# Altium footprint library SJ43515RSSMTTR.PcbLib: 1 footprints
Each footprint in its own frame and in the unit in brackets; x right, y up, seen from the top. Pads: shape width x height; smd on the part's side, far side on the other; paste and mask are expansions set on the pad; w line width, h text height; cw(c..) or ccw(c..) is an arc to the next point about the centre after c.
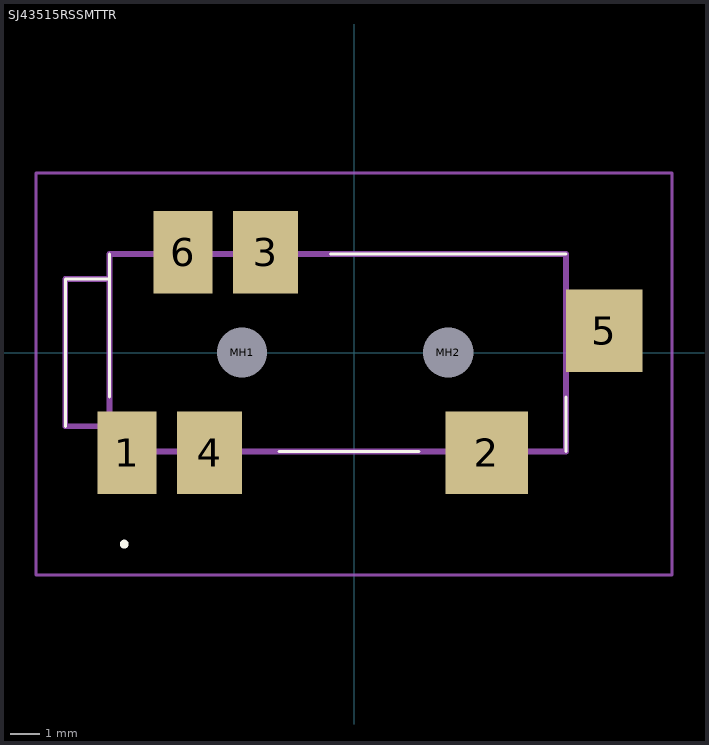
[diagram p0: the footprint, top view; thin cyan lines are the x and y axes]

## SJ43515RSSMTTR [mm]
pads (8):
  rect 2x2.8 smd: 1(-7.7,-3.4) 6(-5.8,3.4)
  rect 2.8x2.8 smd: 2(4.5,-3.4)
  rect 2.2x2.8 smd: 3(-3,3.4) 4(-4.9,-3.4)
  rect 2.6x2.8 smd: 5(8.5,0.75)
  round 0.85 hole 1.7 unplated: MH1(-3.8,0) MH2(3.2,0)
Top Overlay:
  lines w0.1: -9.8,-2.5 -9.8,-2.5 ; -9.8,-2.5 -9.8,2.5 ; -9.8,-2.5 -9.8,2.5 ; -9.8,2.5 -8.3,2.5 ; -9.8,2.5 -8.3,2.5 ; -9.8,2.5 -9.8,2.5 ; -9.8,2.5 -9.8,2.5 ; -8.3,-1.5 -8.3,-1.5 ; -8.3,-1.5 -8.3,3.35 ; -8.3,-1.5 -8.3,3.35 ; -8.3,2.5 -8.3,2.5 ; -8.3,3.35 -8.3,3.35 ; -2.55,-3.35 2.2,-3.35 ; -2.55,-3.35 -2.55,-3.35 ; -2.55,-3.35 2.2,-3.35 ; -0.8,3.35 7.2,3.35 ; -0.8,3.35 7.2,3.35 ; -0.8,3.35 -0.8,3.35 ; 2.2,-3.35 2.2,-3.35 ; 7.2,-3.35 7.2,-1.5 ; 7.2,-3.35 7.2,-3.35 ; 7.2,-3.35 7.2,-1.5 ; 7.2,-1.5 7.2,-1.5 ; 7.2,3.35 7.2,3.35
  lines w0.2: -7.85,-6.5 -7.85,-6.5 ; -7.85,-6.5 ccw(c-7.8,-6.5) -7.75,-6.5 ; -7.85,-6.5 cw(c-7.8,-6.5) -7.75,-6.5 ; -7.85,-6.5 -7.85,-6.5 ; -7.85,-6.5 ccw(c-7.8,-6.5) -7.75,-6.5 ; -7.75,-6.5 -7.75,-6.5
Mechanical 15:
  lines w0.2: -9.8,-2.5 -9.8,2.5 -8.3,2.5 -8.3,-2.5 -9.8,-2.5 ; -8.3,-3.35 7.2,-3.35 7.2,3.35 -8.3,3.35 -8.3,-3.35
Mechanical 20:
  lines w0.1: -10.8,-7.55 10.8,-7.55 10.8,6.1 -10.8,6.1 -10.8,-7.55
3D body "SJ-43515RS-SMT-TR.stp": height 5.8, standoff -4.65, extent -10,-3.376 10,3.376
